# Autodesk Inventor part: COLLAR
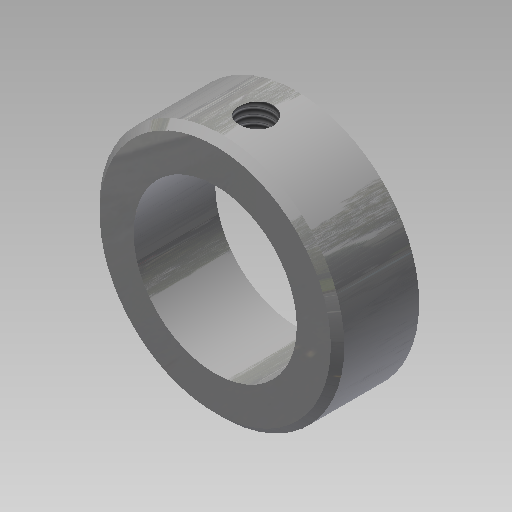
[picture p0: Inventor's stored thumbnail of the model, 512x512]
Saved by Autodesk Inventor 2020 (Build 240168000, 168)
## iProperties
Part Number: COLLAR
Document SubType Name: Modeling
Created: 2003-11
Designer: Autodesk, Inc.
Manufacturer: Standard
Standards Organization: Custom
Mass: 25.9643 g
Surface Area: 21.2895 cm^2
Volume: 3.30755 cm^3
Density: 7.85 g/cm^3
Material: Steel, Mild
Appearance: Steel
Control State: 0
Master: False
Checked Out: False
Shininess: 64.0
Length Units: 11272
Angle Units: 11279
Time Units: 11290
Mass Units: 11286
Length Display Precision: 3
Angle Display Precision: 2
Compacted: True
Density: 0.0
Volumn: 0.0
Area: 0.0
PropertySet Name: Model Information
Author: Autodesk, Inc.
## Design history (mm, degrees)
sketch "Sketch1"
  geometry: C1 r 14.287 at (0, 0); C2 r 9.525 at (0, 0); 1 further point
  constraints: 2 centre point, 2 coincident
  dimensions: "d0" = 28.575 diameter of C1; "d1" = 19.05 diameter of C2
extrude "Extrusion1" new body sketch "Sketch1" distance "d2" = 9.525; taper "d3" = 0 deg
chamfer "Chamfer1" distance "d4" = 0.7874; stored, may be unused: second distance "d5" = 3.175, angle "d16" = 45 deg
sketch "Sketch3"
  geometry: L1 (-14.287, 0)-(14.287, 0) reference; L2 (14.287, 8.738)-(-14.287, 8.738) reference; L3 (14.287, 0)-(14.287, 8.738) reference; L4 (-14.287, 0)-(-14.287, 8.738) reference; L5 (0, 0)-(0, 8.738); 1 further point
  constraints: 2 end point, 2 midpoint, 1 point on line
  dimensions: "d8" = 4.7625 distance from line of L1 point (0, 4.763)
hole "Hole1" sketch "Sketch3" at (0, 4.763) diameter "d9" = 3.9624; stored, may be unused: countersink angle "d13" = 82 deg, drill point angle "d15" = 118 deg; dims "d10" = 12.7, "d11" = 9.525, "d12" = 6.35, "d14" = 19.05
body "Solid1"
